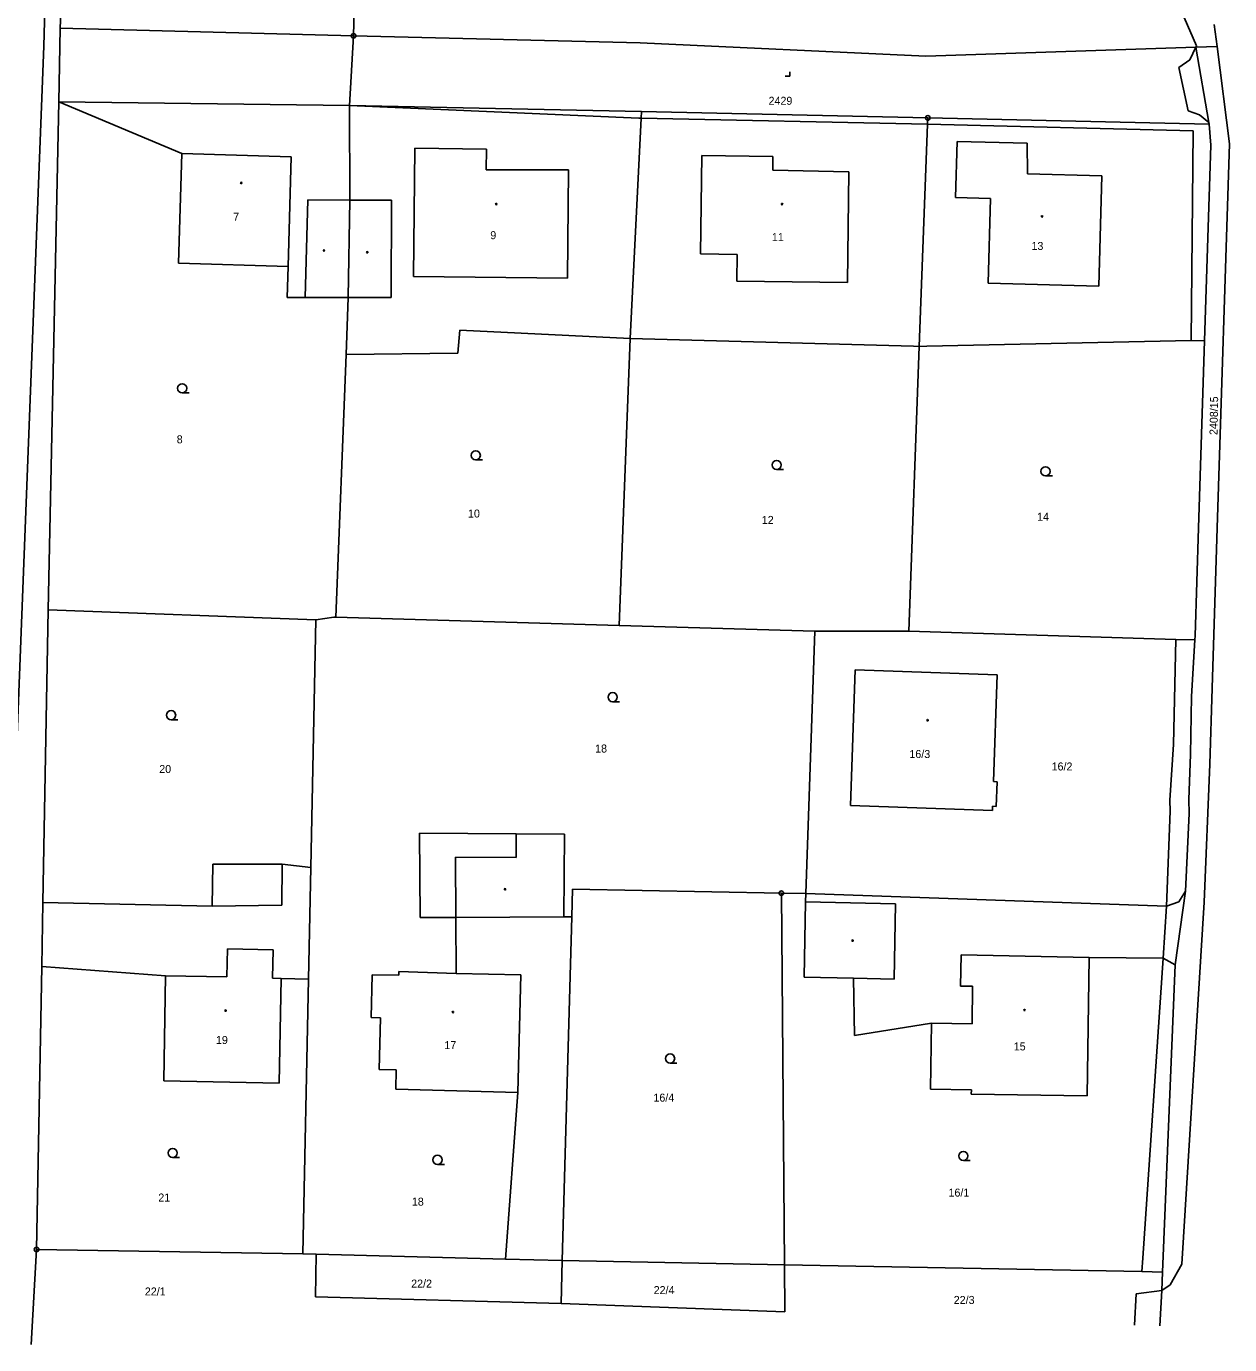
# Model space of a CAD drawing. Extents: x -454285 to -453563, y -1108687 to -1108249.
# Drawn here: x -453760.9 to -453655.7, y -1108662.2 to -1108546.8 of the extents above; entities that cross this region are included whole.
import ezdxf

# ---------------------------------------------------------------- set-up
doc = ezdxf.new("R2010")
doc.units = 0
for name, color, linetype in [('1', 7, 'Continuous'), ('14', 7, 'Continuous'), ('15', 7, 'Continuous'), ('16', 7, 'Continuous'), ('2', 7, 'Continuous'), ('23', 7, 'Continuous'), ('25', 7, 'Continuous'), ('28', 7, 'Continuous')]:
    doc.layers.add(name, color=color, linetype=linetype)

# ---------------------------------------------------------------- blocks, each defined once
blk = doc.blocks.new('Z402')
for start, end in [(0, 180), (180, 0)]:
    blk.add_arc((0, 0), 0.15, start, end)
blk = doc.blocks.new('Z105')
for radius in [0.5, 0.01]:
    blk.add_circle((0, 0), radius)
blk = doc.blocks.new('Z3040')
blk.add_line((1.5, 0), (0, 0))
blk.add_circle((0, 1), 1)
blk = doc.blocks.new('Z319')
for p in [(-1, 0), (0, 1)]:
    blk.add_line(p, (0, 0))

msp = doc.modelspace()

# ---------------------------------------------------------------- linework, layer by layer
at = {"layer": '1'}
for p, q in [((-453757.29, -1108528.36), (-453757.97, -1108546.98)), ((-453732.31, -1108547.66), (-453731.87, -1108531.66)), ((-453663.12, -1108538.12), (-453658.57, -1108548.53)), ((-453757.97, -1108546.98), (-453758.1, -1108553.44)), ((-453757.97, -1108546.98), (-453732.31, -1108547.66)), ((-453657.03, -1108546.68), (-453656.78, -1108548.59)), ((-453732.66, -1108553.75), (-453732.31, -1108547.66)), ((-453732.31, -1108547.66), (-453707.23, -1108548.27)), ((-453707.23, -1108548.27), (-453682.25, -1108549.44)), ((-453658.62, -1108548.65), (-453682.25, -1108549.44)), ((-453658.57, -1108548.53), (-453658.62, -1108548.65)), ((-453656.78, -1108548.59), (-453658.62, -1108548.65)), ((-453658.62, -1108548.65), (-453657.5, -1108555.23)), ((-453656.78, -1108548.59), (-453655.68, -1108557.12)), ((-453758.1, -1108553.44), (-453759.03, -1108597.87)), ((-453758.1, -1108553.44), (-453747.33, -1108557.96)), ((-453732.63, -1108562.03), (-453732.66, -1108553.75)), ((-453707.12, -1108554.28), (-453732.66, -1108553.75)), ((-453707.15, -1108554.87), (-453708.11, -1108574.14)), ((-453707.12, -1108554.28), (-453707.15, -1108554.87)), ((-453682.08, -1108554.84), (-453707.12, -1108554.28)), ((-453682.82, -1108574.83), (-453682.1, -1108555.39)), ((-453682.1, -1108555.39), (-453682.08, -1108554.84)), ((-453682.08, -1108554.84), (-453657.48, -1108555.4)), ((-453657.5, -1108555.23), (-453657.48, -1108555.4)), ((-453657.31, -1108557.22), (-453657.48, -1108555.4)), ((-453657.31, -1108557.22), (-453657.88, -1108574.35)), ((-453656.78, -1108590.71), (-453655.68, -1108557.12)), ((-453747.33, -1108557.96), (-453747.62, -1108567.56)), ((-453732.63, -1108562.03), (-453732.78, -1108570.55)), ((-453747.62, -1108567.56), (-453738.04, -1108567.85)), ((-453738.04, -1108567.85), (-453738.12, -1108570.54)), ((-453738.12, -1108570.54), (-453736.54, -1108570.54)), ((-453736.54, -1108570.54), (-453732.78, -1108570.55)), ((-453732.97, -1108575.53), (-453732.78, -1108570.55)), ((-453723, -1108573.42), (-453723.18, -1108575.42)), ((-453708.11, -1108574.14), (-453723, -1108573.42)), ((-453708.11, -1108574.14), (-453709.08, -1108599.25)), ((-453683.34, -1108574.81), (-453708.11, -1108574.14)), ((-453683.75, -1108599.74), (-453682.82, -1108574.83)), ((-453682.82, -1108574.83), (-453683.34, -1108574.81)), ((-453682.17, -1108574.81), (-453682.82, -1108574.83)), ((-453659.05, -1108574.31), (-453682.17, -1108574.81)), ((-453659.05, -1108574.31), (-453657.88, -1108574.35)), ((-453657.88, -1108574.35), (-453658.41, -1108590.69)), ((-453732.97, -1108575.53), (-453733.85, -1108598.53)), ((-453723.18, -1108575.42), (-453732.97, -1108575.53)), ((-453658.41, -1108590.69), (-453658.69, -1108600.16)), ((-453656.78, -1108590.71), (-453657.19, -1108604.72)), ((-453759.03, -1108597.87), (-453759.49, -1108623.48)), ((-453759.03, -1108597.87), (-453735.61, -1108598.74)), ((-453736.05, -1108620.43), (-453735.61, -1108598.74)), ((-453735.61, -1108598.74), (-453734.05, -1108598.52)), ((-453734.05, -1108598.52), (-453733.85, -1108598.53)), ((-453733.85, -1108598.53), (-453709.08, -1108599.25)), ((-453709.08, -1108599.25), (-453691.95, -1108599.74)), ((-453692.74, -1108622.7), (-453691.95, -1108599.74)), ((-453691.95, -1108599.74), (-453683.75, -1108599.74)), ((-453683.75, -1108599.74), (-453660.38, -1108600.46)), ((-453658.69, -1108600.16), (-453658.71, -1108600.51)), ((-453660.38, -1108600.46), (-453658.71, -1108600.51)), ((-453658.71, -1108600.51), (-453659.01, -1108605.45)), ((-453688.84, -1108614.98), (-453688.42, -1108603.13)), ((-453688.42, -1108603.13), (-453676.01, -1108603.57)), ((-453676.01, -1108603.57), (-453676.34, -1108612.9)), ((-453657.19, -1108604.72), (-453657.42, -1108611.39)), ((-453659.01, -1108605.45), (-453659.1, -1108610.53)), ((-453659.1, -1108610.53), (-453659.24, -1108614.46)), ((-453657.9, -1108623.45), (-453657.42, -1108611.39)), ((-453676.34, -1108612.9), (-453676.02, -1108612.91)), ((-453676.02, -1108612.91), (-453676.1, -1108615.08)), ((-453676.43, -1108615.42), (-453688.84, -1108614.98)), ((-453676.42, -1108615.06), (-453676.43, -1108615.42)), ((-453676.1, -1108615.08), (-453676.42, -1108615.06)), ((-453659.24, -1108614.46), (-453659.22, -1108615.69)), ((-453659.22, -1108615.69), (-453659.55, -1108622.5)), ((-453718.09, -1108617.47), (-453726.54, -1108617.42)), ((-453726.54, -1108617.42), (-453726.49, -1108624.8)), ((-453713.87, -1108617.49), (-453718.09, -1108617.47)), ((-453713.87, -1108617.49), (-453713.91, -1108624.72)), ((-453744.67, -1108623.81), (-453744.62, -1108620.13)), ((-453744.62, -1108620.13), (-453738.57, -1108620.12)), ((-453738.57, -1108620.12), (-453736.05, -1108620.43)), ((-453736.25, -1108630.18), (-453736.05, -1108620.43)), ((-453713.22, -1108624.72), (-453713.15, -1108622.32)), ((-453713.15, -1108622.32), (-453694.89, -1108622.66)), ((-453694.89, -1108622.66), (-453692.74, -1108622.7)), ((-453694.89, -1108622.66), (-453694.62, -1108655.18)), ((-453692.78, -1108623.42), (-453692.88, -1108630.02)), ((-453692.74, -1108622.7), (-453692.78, -1108623.42)), ((-453661.21, -1108623.8), (-453692.74, -1108622.7)), ((-453661.21, -1108623.8), (-453660.13, -1108623.43)), ((-453660.43, -1108628.93), (-453659.55, -1108622.5)), ((-453660.13, -1108623.43), (-453659.55, -1108622.5)), ((-453657.9, -1108623.45), (-453659.85, -1108655.12)), ((-453759.49, -1108623.48), (-453759.59, -1108629.08)), ((-453759.49, -1108623.48), (-453744.67, -1108623.81)), ((-453723.37, -1108624.78), (-453726.49, -1108624.8)), ((-453723.37, -1108624.78), (-453723.34, -1108629.68)), ((-453713.22, -1108624.72), (-453714.05, -1108654.81)), ((-453713.91, -1108624.72), (-453713.22, -1108624.72)), ((-453759.59, -1108629.08), (-453760.04, -1108653.84)), ((-453759.59, -1108629.08), (-453748.75, -1108629.89)), ((-453668.15, -1108640.4), (-453667.96, -1108628.29)), ((-453661.5, -1108628.34), (-453667.96, -1108628.29)), ((-453661.55, -1108655.81), (-453660.43, -1108628.93)), ((-453661.5, -1108628.34), (-453660.43, -1108628.93)), ((-453748.75, -1108629.89), (-453748.92, -1108639.09)), ((-453738.65, -1108630.13), (-453738.82, -1108639.28)), ((-453736.25, -1108630.18), (-453738.65, -1108630.13)), ((-453736.74, -1108654.22), (-453736.25, -1108630.18)), ((-453730.77, -1108633.55), (-453730.67, -1108629.81)), ((-453730.67, -1108629.81), (-453728.36, -1108629.83)), ((-453728.36, -1108629.83), (-453728.35, -1108629.53)), ((-453723.34, -1108629.68), (-453728.35, -1108629.53)), ((-453692.88, -1108630.02), (-453688.59, -1108630.11)), ((-453688.59, -1108630.11), (-453688.49, -1108635.12)), ((-453729.95, -1108633.57), (-453730.77, -1108633.55)), ((-453730.07, -1108638.09), (-453729.95, -1108633.57)), ((-453681.76, -1108634.04), (-453688.49, -1108635.12)), ((-453681.84, -1108639.82), (-453681.76, -1108634.04)), ((-453728.57, -1108638.13), (-453730.07, -1108638.09)), ((-453728.62, -1108639.8), (-453728.57, -1108638.13)), ((-453738.82, -1108639.28), (-453748.92, -1108639.09)), ((-453717.95, -1108640.09), (-453728.62, -1108639.8)), ((-453719.03, -1108654.68), (-453717.95, -1108640.09)), ((-453678.27, -1108639.87), (-453681.84, -1108639.82)), ((-453678.28, -1108640.25), (-453678.27, -1108639.87)), ((-453668.15, -1108640.4), (-453678.28, -1108640.25)), ((-453760.52, -1108662.16), (-453760.04, -1108653.84)), ((-453760.04, -1108653.84), (-453736.74, -1108654.22)), ((-453736.74, -1108654.22), (-453735.58, -1108654.24)), ((-453735.58, -1108654.24), (-453735.65, -1108657.97)), ((-453735.58, -1108654.24), (-453719.03, -1108654.68)), ((-453719.03, -1108654.68), (-453714.05, -1108654.81)), ((-453714.05, -1108654.81), (-453714.15, -1108658.56)), ((-453714.05, -1108654.81), (-453694.62, -1108655.18)), ((-453694.62, -1108655.18), (-453663.37, -1108655.77)), ((-453694.62, -1108655.18), (-453694.59, -1108659.3)), ((-453659.85, -1108655.12), (-453660.88, -1108656.94)), ((-453663.37, -1108655.77), (-453661.55, -1108655.81)), ((-453661.62, -1108657.43), (-453661.55, -1108655.81)), ((-453735.65, -1108657.97), (-453714.15, -1108658.56)), ((-453661.62, -1108657.43), (-453661.79, -1108660.53)), ((-453660.88, -1108656.94), (-453661.62, -1108657.43)), ((-453714.15, -1108658.56), (-453694.59, -1108659.3))]:
    msp.add_line(p, q, dxfattribs=at)
at = {"layer": '2'}
for p, q in [((-453757.83, -1108485.39), (-453759.39, -1108548.56)), ((-453759.39, -1108548.56), (-453762.28, -1108623.18)), ((-453658.62, -1108548.65), (-453659.15, -1108549.75)), ((-453659.15, -1108549.75), (-453660.12, -1108550.43)), ((-453660.12, -1108550.43), (-453659.31, -1108554.23)), ((-453732.66, -1108553.75), (-453758.1, -1108553.44)), ((-453707.37, -1108554.87), (-453732.66, -1108553.75)), ((-453659.31, -1108554.23), (-453658.3, -1108554.57)), ((-453707.37, -1108554.87), (-453707.15, -1108554.87)), ((-453707.15, -1108554.87), (-453682.1, -1108555.39)), ((-453682.1, -1108555.39), (-453658.86, -1108555.96)), ((-453658.3, -1108554.57), (-453657.5, -1108555.23)), ((-453658.86, -1108555.96), (-453659.05, -1108574.31)), ((-453727.07, -1108568.7), (-453726.95, -1108557.49)), ((-453726.95, -1108557.49), (-453720.68, -1108557.56)), ((-453720.68, -1108557.56), (-453720.7, -1108559.37)), ((-453679.66, -1108561.81), (-453679.52, -1108556.89)), ((-453679.52, -1108556.89), (-453673.38, -1108557.06)), ((-453673.38, -1108557.06), (-453673.37, -1108559.72)), ((-453747.33, -1108557.96), (-453737.76, -1108558.25)), ((-453737.76, -1108558.25), (-453738.04, -1108567.85)), ((-453701.95, -1108566.74), (-453701.86, -1108558.14)), ((-453701.86, -1108558.14), (-453695.63, -1108558.21)), ((-453695.63, -1108558.21), (-453695.64, -1108559.41)), ((-453720.7, -1108559.37), (-453713.5, -1108559.37)), ((-453713.5, -1108559.37), (-453713.6, -1108568.85)), ((-453695.64, -1108559.41), (-453689, -1108559.55)), ((-453689, -1108559.55), (-453689.1, -1108569.23)), ((-453673.37, -1108559.72), (-453666.87, -1108559.9)), ((-453666.87, -1108559.9), (-453667.13, -1108569.56)), ((-453736.54, -1108570.54), (-453736.3, -1108562.02)), ((-453736.3, -1108562.02), (-453732.63, -1108562.03)), ((-453732.63, -1108562.03), (-453728.98, -1108562.03)), ((-453728.98, -1108562.03), (-453729.02, -1108570.55)), ((-453676.6, -1108561.9), (-453679.66, -1108561.81)), ((-453676.8, -1108569.29), (-453676.6, -1108561.9)), ((-453698.75, -1108566.78), (-453701.95, -1108566.74)), ((-453698.77, -1108569.13), (-453698.75, -1108566.78)), ((-453713.6, -1108568.85), (-453727.07, -1108568.7)), ((-453689.1, -1108569.23), (-453698.77, -1108569.13)), ((-453667.13, -1108569.56), (-453676.8, -1108569.29)), ((-453729.02, -1108570.55), (-453732.78, -1108570.55)), ((-453660.58, -1108609.65), (-453660.38, -1108600.46)), ((-453660.58, -1108609.65), (-453660.92, -1108614.53)), ((-453660.92, -1108614.53), (-453660.89, -1108615.5)), ((-453661.21, -1108623.8), (-453660.89, -1108615.5)), ((-453718.09, -1108617.47), (-453718.1, -1108619.55)), ((-453723.37, -1108624.78), (-453723.4, -1108619.51)), ((-453723.4, -1108619.51), (-453718.1, -1108619.55)), ((-453738.58, -1108623.72), (-453738.57, -1108620.12)), ((-453692.78, -1108623.42), (-453684.89, -1108623.59)), ((-453744.67, -1108623.81), (-453738.58, -1108623.72)), ((-453684.89, -1108623.59), (-453685.03, -1108630.18)), ((-453661.21, -1108623.8), (-453661.5, -1108628.34)), ((-453723.37, -1108624.78), (-453713.91, -1108624.72)), ((-453743.39, -1108629.99), (-453743.34, -1108627.53)), ((-453743.34, -1108627.53), (-453739.34, -1108627.61)), ((-453739.34, -1108627.61), (-453739.39, -1108630.09)), ((-453679.17, -1108628.05), (-453679.21, -1108630.8)), ((-453667.96, -1108628.29), (-453679.17, -1108628.05)), ((-453661.5, -1108628.34), (-453663.28, -1108654.61)), ((-453748.75, -1108629.89), (-453743.39, -1108629.99)), ((-453739.39, -1108630.09), (-453738.65, -1108630.13)), ((-453723.34, -1108629.68), (-453717.67, -1108629.82)), ((-453717.67, -1108629.82), (-453717.95, -1108640.09)), ((-453685.03, -1108630.18), (-453688.59, -1108630.11)), ((-453679.21, -1108630.8), (-453678.16, -1108630.81)), ((-453678.2, -1108634.09), (-453678.16, -1108630.81)), ((-453681.76, -1108634.04), (-453678.2, -1108634.09)), ((-453663.28, -1108654.61), (-453663.37, -1108655.77)), ((-453663.85, -1108657.73), (-453663.99, -1108660.45)), ((-453661.62, -1108657.43), (-453663.85, -1108657.73))]:
    msp.add_line(p, q, dxfattribs=at)

# ---------------------------------------------------------------- block references
at = {"layer": '23', "xscale": 0.4, "yscale": 0.4000000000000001}
for name, p in [('Z319', (-453694.15, -1108551.2)), ('Z3040', (-453747.3, -1108578.89)), ('Z3040', (-453721.62, -1108584.76)), ('Z3040', (-453695.3, -1108585.6)), ('Z3040', (-453671.78, -1108586.16)), ('Z3040', (-453709.65, -1108605.92)), ('Z3040', (-453748.27, -1108607.49)), ('Z3040', (-453704.62, -1108637.53)), ('Z3040', (-453748.13, -1108645.79)), ('Z3040', (-453678.97, -1108646.05)), ('Z3040', (-453724.97, -1108646.39))]:
    msp.add_blockref(name, p, dxfattribs=at)
at = {"layer": '25', "xscale": 0.4, "yscale": 0.4000000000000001}
for p in [(-453742.14, -1108560.53), (-453719.83, -1108562.38), (-453694.82, -1108562.38), (-453672.09, -1108563.46), (-453734.89, -1108566.44), (-453731.11, -1108566.59), (-453682.1, -1108607.53), (-453719.06, -1108622.32), (-453688.66, -1108626.81), (-453743.5, -1108632.94), (-453723.62, -1108633.07), (-453673.62, -1108632.89)]:
    msp.add_blockref('Z402', p, dxfattribs=at)
at = {"layer": '28', "xscale": 0.4, "yscale": 0.4000000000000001}
for p in [(-453732.31, -1108547.66), (-453682.08, -1108554.84), (-453694.89, -1108622.66), (-453760.04, -1108653.84)]:
    msp.add_blockref('Z105', p, dxfattribs=at)

# ---------------------------------------------------------------- texts
at = {"layer": '14'}
msp.add_text('2408/15', height=0.7, rotation=88.92, dxfattribs=at).set_placement((-453656.74, -1108582.59))
for s, p in [('8', (-453747.78, -1108583.31)), ('10', (-453722.3, -1108589.8)), ('12', (-453696.6, -1108590.36)), ('14', (-453672.52, -1108590.08)), ('18', (-453711.18, -1108610.36)), ('20', (-453749.31, -1108612.15)), ('16/2', (-453671.25, -1108611.93)), ('16/4', (-453706.08, -1108640.9)), ('16/1', (-453680.27, -1108649.21)), ('21', (-453749.39, -1108649.64)), ('22/2', (-453727.27, -1108657.17)), ('22/1', (-453750.57, -1108657.86)), ('22/4', (-453706.06, -1108657.74)), ('22/3', (-453679.81, -1108658.6))]:
    msp.add_text(s, height=0.7, dxfattribs=at).set_placement(p)
at = {"layer": '15'}
for s, p in [('2429', (-453696.01, -1108553.69)), ('7', (-453742.84, -1108563.84)), ('9', (-453720.35, -1108565.45)), ('11', (-453695.72, -1108565.62)), ('13', (-453673.01, -1108566.39)), ('16/3', (-453683.69, -1108610.84)), ('19', (-453744.35, -1108635.86)), ('17', (-453724.37, -1108636.31)), ('15', (-453674.56, -1108636.42))]:
    msp.add_text(s, height=0.7, dxfattribs=at).set_placement(p)
at = {"layer": '16'}
msp.add_text('18', height=0.7, dxfattribs=at).set_placement((-453727.21, -1108650))

doc.saveas('drawing.dxf')
